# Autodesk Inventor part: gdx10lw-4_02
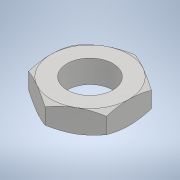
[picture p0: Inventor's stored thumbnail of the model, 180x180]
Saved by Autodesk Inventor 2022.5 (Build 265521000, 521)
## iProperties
Part Number: gdx10lw-4_02
Material: 一般
Document SubType Name: Modeling
Designer: ImaoCorp
Density: 1 g/cm^3
Appearance: 既定
Author: ImaoCorp
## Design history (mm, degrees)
feature "gdx10lw-4_02"
node "ソリッド1"
